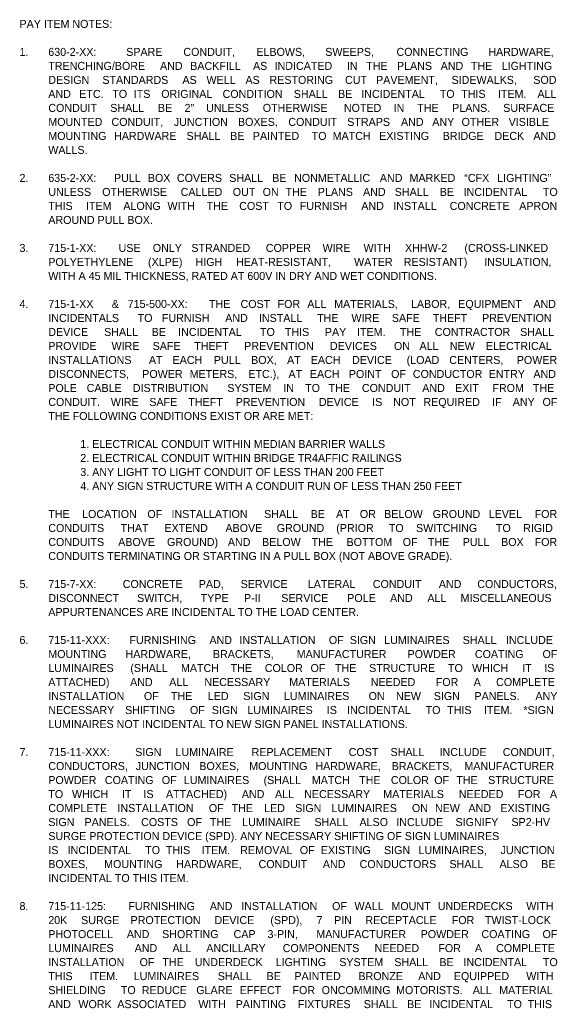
# Model space of a CAD drawing. Extents: x -55 to 2471539, y -90 to 3608906.
# Drawn here: x 27 to 497, y 2532 to 3397 of the extents above; entities that cross this region are included whole.
import ezdxf

# ---------------------------------------------------------------- set-up
doc = ezdxf.new("R2010")
doc.units = 0
doc.layers.add('XSCell', color=7, linetype='Continuous')

msp = doc.modelspace()

# ---------------------------------------------------------------- texts
at = {"layer": 'XSCell'}
for s, p in [('PAY ITEM NOTES:', (26.68, 3389.74)), ('630-2-XX: ', (51.88, 3365.24)), ('SPARE ', (120.08, 3365.24)), ('CONDUIT, ', (170.11, 3365.24)), ('ELBOWS, ', (233.99, 3365.24)), ('SWEEPS, ', (294.28, 3365.24)), ('CONNECTING ', (356.65, 3365.24)), ('1.', (26.68, 3365.24)), ('HARDWARE, ', (437.06, 3365.24)), ('TRENCHING/BORE ', (51.88, 3352.99)), ('AND ', (149.66, 3352.99)), ('BACKFILL ', (176.11, 3352.99)), ('AS ', (231.06, 3352.99)), ('INDICATED ', (249.96, 3352.99)), ('IN ', (313.22, 3352.99)), ('THE ', (330.09, 3352.99)), ('PLANS ', (357.07, 3352.99)), ('AND ', (395.32, 3352.99)), ('THE ', (421.77, 3352.99)), ('LIGHTING ', (448.75, 3352.99)), ('DESIGN ', (51.88, 3340.74)), ('STANDARDS ', (99.2, 3340.74)), ('AS ', (169.29, 3340.74)), ('WELL ', (190.33, 3340.74)), ('AS ', (224.46, 3340.74)), ('RESTORING ', (245.49, 3340.74)), ('CUT ', (311.63, 3340.74)), ('PAVEMENT, ', (338.81, 3340.74)), ('SIDEWALKS, ', (404.84, 3340.74)), ('SOD ', (476.42, 3340.74)), ('AND ', (51.88, 3328.49)), ('ETC. ', (78.98, 3328.49)), ('TO ', (107.88, 3328.49)), ('ITS ', (126.69, 3328.49)), ('ORIGINAL ', (150.74, 3328.49)), ('CONDITION ', (204.43, 3328.49)), ('SHALL ', (266.79, 3328.49)), ('BE ', (305.52, 3328.49)), ('INCIDENTAL ', (325.8, 3328.49)), ('TO ', (394.52, 3328.49)), ('THIS ', (413.34, 3328.49)), ('ITEM. ', (445.46, 3328.49)), ('ALL ', (480.05, 3328.49)), ('CONDUIT ', (51.88, 3316.24)), ('SHALL ', (106.12, 3316.24)), ('BE ', (147.86, 3316.24)), ('2” ', (171.15, 3316.24)), ('UNLESS ', (190.04, 3316.24)), ('OTHERWISE ', (239.61, 3316.24)), ('NOTED ', (310.61, 3316.24)), ('IN ', (354.19, 3316.24)), ('THE ', (374.74, 3316.24)), ('PLANS. ', (405.39, 3316.24)), ('SURFACE ', (450.07, 3316.24)), ('MOUNTED ', (51.88, 3303.99)), ('CONDUIT, ', (107.18, 3303.99)), ('JUNCTION ', (161.77, 3303.99)), ('BOXES, ', (217.91, 3303.99)), ('CONDUIT ', (262.01, 3303.99)), ('STRAPS ', (313.55, 3303.99)), ('AND ', (360.6, 3303.99)), ('ANY ', (388, 3303.99)), ('OTHER ', (413.64, 3303.99)), ('VISIBLE ', (454.83, 3303.99)), ('MOUNTING ', (51.88, 3291.74)), ('HARDWARE ', (109.45, 3291.74)), ('SHALL ', (172.87, 3291.74)), ('BE ', (211.11, 3291.74)), ('PAINTED ', (230.91, 3291.74)), ('TO ', (282.44, 3291.74)), ('MATCH ', (300.77, 3291.74)), ('EXISTING ', (341.5, 3291.74)), ('BRIDGE ', (397.1, 3291.74)), ('DECK ', (442.4, 3291.74)), ('AND ', (476.52, 3291.74)), ('WALLS.', (51.88, 3279.49)), ('2.', (26.68, 3254.99)), ('635-2-XX: ', (51.88, 3254.99)), ('PULL ', (109.38, 3254.99)), ('BOX ', (139.01, 3254.99)), ('COVERS ', (164.44, 3254.99)), ('SHALL ', (210.25, 3254.99)), ('BE ', (247.86, 3254.99)), ('NONMETALLIC ', (267.04, 3254.99)), ('AND ', (342.08, 3254.99)), ('MARKED ', (368.08, 3254.99)), ('“CFX ', (416.03, 3254.99)), ('LIGHTING” ', (444.82, 3254.99)), ('UNLESS ', (51.88, 3242.74)), ('OTHERWISE ', (99.08, 3242.74)), ('CALLED ', (167.72, 3242.74)), ('OUT ', (213.33, 3242.74)), ('ON ', (239.5, 3242.74)), ('THE ', (259.52, 3242.74)), ('PLANS ', (287.82, 3242.74)), ('AND ', (327.38, 3242.74)), ('SHALL ', (355.13, 3242.74)), ('BE ', (394.51, 3242.74)), ('INCIDENTAL ', (415.44, 3242.74)), ('TO ', (484.81, 3242.74)), ('THIS ', (51.88, 3230.49)), ('ITEM ', (84.87, 3230.49)), ('ALONG ', (117.57, 3230.49)), ('WITH ', (156.2, 3230.49)), ('THE ', (190.47, 3230.49)), ('COST ', (218.99, 3230.49)), ('TO ', (252.31, 3230.49)), ('FURNISH ', (272, 3230.49)), ('AND ', (325.85, 3230.49)), ('INSTALL ', (353.83, 3230.49)), ('CONCRETE ', (403.21, 3230.49)), ('APRON ', (464.1, 3230.49)), ('AROUND PULL BOX.', (51.88, 3218.24)), ('3.', (26.68, 3193.74)), ('715-1-XX: ', (51.88, 3193.74)), ('USE ', (113.41, 3193.74)), ('ONLY ', (143.32, 3193.74)), ('STRANDED ', (177.09, 3193.74)), ('COPPER ', (242.27, 3193.74)), ('WIRE ', (291.93, 3193.74)), ('WITH ', (327.81, 3193.74)), ('XHHW-2 ', (364.13, 3193.74)), ('(CROSS-LINKED ', (416.09, 3193.74)), ('POLYETHYLENE ', (51.88, 3181.49)), ('(XLPE) ', (139.17, 3181.49)), ('HIGH ', (180.77, 3181.49)), ('HEAT-RESISTANT, ', (216.17, 3181.49)), ('WATER ', (319.51, 3181.49)), ('RESISTANT) ', (362.99, 3181.49)), ('INSULATION, ', (433.46, 3181.49)), ('WITH A 45 MIL THICKNESS, RATED AT 600V IN DRY AND WET CONDITIONS.', (51.88, 3169.24)), ('4.', (26.68, 3144.74)), ('715-1-XX ', (51.88, 3144.74)), ('& ', (107.43, 3144.74)), ('715-500-XX: ', (121.38, 3144.74)), ('THE ', (192.53, 3144.74)), ('COST ', (220.15, 3144.74)), ('FOR ', (252.57, 3144.74)), ('ALL ', (278.57, 3144.74)), ('MATERIALS, ', (302.12, 3144.74)), ('LABOR, ', (369.32, 3144.74)), ('EQUIPMENT ', (410.7, 3144.74)), ('AND ', (476.52, 3144.74)), ('INCIDENTALS ', (51.88, 3132.49)), ('TO ', (130.09, 3132.49)), ('FURNISH ', (151.32, 3132.49)), ('AND ', (206.72, 3132.49)), ('INSTALL ', (236.24, 3132.49)), ('THE ', (287.15, 3132.49)), ('WIRE ', (317.21, 3132.49)), ('SAFE ', (352.59, 3132.49)), ('THEFT ', (388.42, 3132.49)), ('PREVENTION ', (431.57, 3132.49)), ('DEVICE ', (51.88, 3120.24)), ('SHALL ', (100.73, 3120.24)), ('BE ', (142.37, 3120.24)), ('INCIDENTAL ', (165.56, 3120.24)), ('TO ', (237.2, 3120.24)), ('THIS ', (258.92, 3120.24)), ('PAY ', (293.95, 3120.24)), ('ITEM. ', (322.14, 3120.24)), ('THE ', (359.64, 3120.24)), ('CONTRACTOR ', (390.2, 3120.24)), ('SHALL ', (464.9, 3120.24)), ('PROVIDE ', (51.88, 3107.99)), ('WIRE ', (107.23, 3107.99)), ('SAFE ', (143.2, 3107.99)), ('THEFT ', (179.61, 3107.99)), ('PREVENTION ', (223.35, 3107.99)), ('DEVICES ', (298.41, 3107.99)), ('ON ', (354.43, 3107.99)), ('ALL ', (376.8, 3107.99)), ('NEW ', (403.38, 3107.99)), ('ELECTRICAL ', (434.87, 3107.99)), ('INSTALLATIONS ', (51.88, 3095.74)), ('AT ', (139.95, 3095.74)), ('EACH ', (160.68, 3095.74)), ('PULL ', (196.8, 3095.74)), ('BOX, ', (229.41, 3095.74)), ('AT ', (260.88, 3095.74)), ('EACH ', (281.61, 3095.74)), ('DEVICE ', (317.73, 3095.74)), ('(LOAD ', (365.55, 3095.74)), ('CENTERS, ', (402.86, 3095.74)), ('POWER ', (461.96, 3095.74)), ('DISCONNECTS, ', (51.88, 3083.49)), ('POWER ', (134.11, 3083.49)), ('METERS, ', (175.64, 3083.49)), ('ETC.), ', (226.96, 3083.49)), ('AT ', (262.13, 3083.49)), ('EACH ', (280.84, 3083.49)), ('POINT ', (314.95, 3083.49)), ('OF ', (351.95, 3083.49)), ('CONDUCTOR ', (370.97, 3083.49)), ('ENTRY ', (437.34, 3083.49)), ('AND ', (476.52, 3083.49)), ('POLE ', (51.88, 3071.24)), ('CABLE ', (85.46, 3071.24)), ('DISTRIBUTION ', (125.86, 3071.24)), ('SYSTEM ', (208.6, 3071.24)), ('TO ', (276.72, 3071.24)), ('CONDUIT ', (326.37, 3071.24)), ('FROM ', (440.63, 3071.24)), ('IN ', (257.59, 3071.24)), ('THE ', (297.13, 3071.24)), ('AND ', (379.2, 3071.24)), ('EXIT ', (407.9, 3071.24)), ('THE ', (475.98, 3071.24)), ('CONDUIT. ', (51.88, 3058.99)), ('WIRE ', (106.6, 3058.99)), ('SAFE ', (140.29, 3058.99)), ('THEFT ', (174.43, 3058.99)), ('PREVENTION ', (215.9, 3058.99)), ('DEVICE ', (288.69, 3058.99)), ('IS ', (335.36, 3058.99)), ('NOT ', (353.76, 3058.99)), ('REQUIRED ', (380.24, 3058.99)), ('IF ', (440.35, 3058.99)), ('ANY ', (458.4, 3058.99)), ('OF ', (484.48, 3058.99)), ('THE FOLLOWING CONDITIONS EXIST OR ARE MET:', (51.88, 3046.74)), ('1. ELECTRICAL CONDUIT WITHIN MEDIAN BARRIER WALLS', (79.88, 3022.24)), ('2. ELECTRICAL CONDUIT WITHIN BRIDGE TR4AFFIC RAILINGS', (79.88, 3009.99)), ('3. ANY LIGHT TO LIGHT CONDUIT OF LESS THAN 200 FEET', (79.88, 2997.74)), ('4. ANY SIGN STRUCTURE WITH A CONDUIT RUN OF LESS THAN 250 FEET', (79.88, 2985.49)), ('THE ', (51.88, 2960.99)), ('LOCATION ', (81.48, 2960.99)), ('OF ', (138.62, 2960.99)), ('INSTALLATION ', (159.73, 2960.99)), ('SHALL ', (240.82, 2960.99)), ('BE ', (281.51, 2960.99)), ('AT ', (303.75, 2960.99)), ('OR ', (324.57, 2960.99)), ('BELOW ', (345.84, 2960.99)), ('GROUND ', (388.35, 2960.99)), ('LEVEL ', (437.37, 2960.99)), ('FOR ', (477.59, 2960.99)), ('CONDUITS ', (51.88, 2948.74)), ('THAT ', (115.22, 2948.74)), ('EXTEND ', (153.55, 2948.74)), ('ABOVE ', (206.93, 2948.74)), ('GROUND ', (251.86, 2948.74)), ('(PRIOR ', (303.94, 2948.74)), ('TO ', (349.91, 2948.74)), ('SWITCHING ', (373.75, 2948.74)), ('TO ', (443.69, 2948.74)), ('RIGID ', (467.53, 2948.74)), ('CONDUITS ', (51.88, 2936.49)), ('ABOVE ', (113.04, 2936.49)), ('GROUND) ', (155.79, 2936.49)), ('AND ', (209.04, 2936.49)), ('BELOW ', (239, 2936.49)), ('THE ', (282.41, 2936.49)), ('BOTTOM ', (312.9, 2936.49)), ('OF ', (362.12, 2936.49)), ('THE ', (384.12, 2936.49)), ('PULL ', (414.62, 2936.49)), ('BOX ', (448.21, 2936.49)), ('FOR ', (477.59, 2936.49)), ('CONDUITS TERMINATING OR STARTING IN A PULL BOX (NOT ABOVE GRADE).', (51.88, 2924.24)), ('5.', (26.68, 2899.74)), ('715-7-XX: ', (51.88, 2899.74)), ('CONCRETE ', (117.03, 2899.74)), ('PAD, ', (183.6, 2899.74)), ('SERVICE ', (220.24, 2899.74)), ('LATERAL ', (279, 2899.74)), ('CONDUIT ', (335.93, 2899.74)), ('AND ', (393.71, 2899.74)), ('CONDUCTORS, ', (427.37, 2899.74)), ('DISCONNECT ', (51.88, 2887.49)), ('SWITCH, ', (129.64, 2887.49)), ('TYPE ', (185.25, 2887.49)), ('P-II ', (223.15, 2887.49)), ('SERVICE ', (255.82, 2887.49)), ('POLE ', (313.56, 2887.49)), ('AND ', (351.06, 2887.49)), ('ALL ', (383.69, 2887.49)), ('MISCELLANEOUS ', (412.79, 2887.49)), ('APPURTENANCES ARE INCIDENTAL TO THE LOAD CENTER.', (51.88, 2875.24)), ('6.', (26.68, 2850.74)), ('715-11-XXX: ', (51.88, 2850.74)), ('FURNISHING ', (122.93, 2850.74)), ('AND ', (192.93, 2850.74)), ('INSTALLATION ', (219.18, 2850.74)), ('OF ', (297.45, 2850.74)), ('SIGN ', (315.74, 2850.74)), ('LUMINAIRES ', (345.9, 2850.74)), ('SHALL ', (414.59, 2850.74)), ('INCLUDE ', (452.46, 2850.74)), ('MOUNTING ', (51.88, 2838.49)), ('HARDWARE, ', (119.48, 2838.49)), ('BRACKETS, ', (195.97, 2838.49)), ('MANUFACTURER ', (269.31, 2838.49)), ('POWDER ', (366.37, 2838.49)), ('COATING ', (425.27, 2838.49)), ('OF ', (484.48, 2838.49)), ('LUMINAIRES ', (51.88, 2826.24)), ('(SHALL ', (123.68, 2826.24)), ('MATCH ', (168.01, 2826.24)), ('THE ', (211.48, 2826.24)), ('COLOR ', (241.38, 2826.24)), ('OF ', (281.43, 2826.24)), ('THE ', (302.84, 2826.24)), ('STRUCTURE ', (332.74, 2826.24)), ('TO ', (401.75, 2826.24)), ('WHICH ', (422.82, 2826.24)), ('IT ', (466.72, 2826.24)), ('IS ', (485.95, 2826.24)), ('ATTACHED) ', (51.88, 2813.99)), ('AND ', (123.47, 2813.99)), ('ALL ', (157.72, 2813.99)), ('NECESSARY ', (188.45, 2813.99)), ('MATERIALS ', (262.81, 2813.99)), ('NEEDED ', (334.12, 2813.99)), ('FOR ', (391.05, 2813.99)), ('A ', (424.22, 2813.99)), ('COMPLETE ', (443.85, 2813.99)), ('INSTALLATION ', (51.88, 2801.74)), ('OF ', (135.58, 2801.74)), ('THE ', (159.31, 2801.74)), ('LED ', (191.53, 2801.74)), ('SIGN ', (222.55, 2801.74)), ('LUMINAIRES ', (258.15, 2801.74)), ('ON ', (332.27, 2801.74)), ('NEW ', (356.22, 2801.74)), ('SIGN ', (389.3, 2801.74)), ('PANELS. ', (424.89, 2801.74)), ('ANY ', (478.27, 2801.74)), ('NECESSARY ', (51.88, 2789.49)), ('SHIFTING ', (119.12, 2789.49)), ('OF ', (175.87, 2789.49)), ('SIGN ', (195.05, 2789.49)), ('LUMINAIRES ', (226.1, 2789.49)), ('IS ', (295.69, 2789.49)), ('INCIDENTAL ', (313.39, 2789.49)), ('TO ', (382.15, 2789.49)), ('THIS ', (400.99, 2789.49)), ('ITEM. ', (433.14, 2789.49)), ('*SIGN ', (467.76, 2789.49)), ('LUMINAIRES NOT INCIDENTAL TO NEW SIGN PANEL INSTALLATIONS.', (51.88, 2777.24)), ('7.', (26.68, 2752.74)), ('715-11-XXX: ', (51.88, 2752.74)), ('SIGN ', (127.98, 2752.74)), ('LUMINAIRE ', (163.19, 2752.74)), ('REPLACEMENT ', (229.85, 2752.74)), ('COST ', (314.81, 2752.74)), ('SHALL ', (351.45, 2752.74)), ('INCLUDE ', (394.36, 2752.74)), ('CONDUIT, ', (449.72, 2752.74)), ('CONDUCTORS, ', (51.88, 2740.49)), ('JUNCTION ', (128.38, 2740.49)), ('BOXES, ', (184.07, 2740.49)), ('MOUNTING ', (227.74, 2740.49)), ('HARDWARE, ', (285.65, 2740.49)), ('BRACKETS, ', (352.46, 2740.49)), ('MANUFACTURER ', (416.11, 2740.49)), ('POWDER ', (51.88, 2728.24)), ('COATING ', (101.4, 2728.24)), ('OF ', (151.24, 2728.24)), ('LUMINAIRES ', (170.57, 2728.24)), ('(SHALL ', (240.3, 2728.24)), ('MATCH ', (282.55, 2728.24)), ('THE ', (323.94, 2728.24)), ('COLOR ', (351.76, 2728.24)), ('OF ', (389.72, 2728.24)), ('THE ', (409.05, 2728.24)), ('STRUCTURE ', (436.87, 2728.24)), ('TO ', (51.88, 2715.99)), ('WHICH ', (72.65, 2715.99)), ('IT ', (116.27, 2715.99)), ('IS ', (135.21, 2715.99)), ('ATTACHED) ', (154.85, 2715.99)), ('AND ', (221.27, 2715.99)), ('ALL ', (250.34, 2715.99)), ('NECESSARY ', (275.89, 2715.99)), ('MATERIALS ', (345.07, 2715.99)), ('NEEDED ', (411.2, 2715.99)), ('FOR ', (462.95, 2715.99)), ('A ', (490.95, 2715.99)), ('COMPLETE ', (51.88, 2703.74)), ('INSTALLATION ', (112.45, 2703.74)), ('OF ', (192.38, 2703.74)), ('THE ', (212.33, 2703.74)), ('LED ', (240.77, 2703.74)), ('SIGN ', (268.01, 2703.74)), ('LUMINAIRES ', (299.83, 2703.74)), ('ON ', (370.17, 2703.74)), ('NEW ', (390.34, 2703.74)), ('AND ', (419.64, 2703.74)), ('EXISTING ', (447.54, 2703.74)), ('SIGN ', (51.88, 2691.49)), ('PANELS. ', (83.62, 2691.49)), ('COSTS ', (133.14, 2691.49)), ('OF ', (173.39, 2691.49)), ('THE ', (193.26, 2691.49)), ('LUMINAIRE ', (221.62, 2691.49)), ('SHALL ', (284.81, 2691.49)), ('ALSO ', (324.26, 2691.49)), ('INCLUDE ', (356.45, 2691.49)), ('SIGNIFY ', (408.34, 2691.49)), ('SP2-HV ', (457.26, 2691.49)), ('SURGE PROTECTION DEVICE (SPD). ANY NECESSARY SHIFTING OF SIGN LUMINAIRES ', (51.88, 2679.24)), ('IS ', (51.88, 2666.99)), ('INCIDENTAL ', (68.77, 2666.99)), ('TO ', (136.7, 2666.99)), ('THIS ', (154.73, 2666.99)), ('ITEM. ', (186.07, 2666.99)), ('REMOVAL ', (219.87, 2666.99)), ('OF ', (272.05, 2666.99)), ('EXISTING ', (290.42, 2666.99)), ('SIGN ', (345.72, 2666.99)), ('LUMINAIRES, ', (375.96, 2666.99)), ('JUNCTION ', (447.79, 2666.99)), ('BOXES, ', (51.88, 2654.74)), ('MOUNTING ', (100.75, 2654.74)), ('HARDWARE, ', (163.88, 2654.74)), ('CONDUIT ', (235.9, 2654.74)), ('AND ', (292.19, 2654.74)), ('CONDUCTORS ', (324.36, 2654.74)), ('SHALL ', (403.02, 2654.74)), ('ALSO ', (446.81, 2654.74)), ('BE ', (483.35, 2654.74)), ('INCIDENTAL TO THIS ITEM.', (51.88, 2642.49)), ('8.', (26.68, 2617.99)), ('715-11-125: ', (51.88, 2617.99)), ('FURNISHING ', (121.99, 2617.99)), ('AND ', (193.26, 2617.99)), ('INSTALLATION ', (220.77, 2617.99)), ('OF ', (300.31, 2617.99)), ('WALL ', (319.87, 2617.99)), ('MOUNT ', (352.21, 2617.99)), ('UNDERDECKS ', (392.8, 2617.99)), ('WITH ', (470.23, 2617.99)), ('20K ', (51.88, 2605.74)), ('SURGE ', (80.64, 2605.74)), ('PROTECTION ', (123.89, 2605.74)), ('DEVICE ', (197.33, 2605.74)), ('(SPD), ', (246.25, 2605.74)), ('7 ', (286.69, 2605.74)), ('PIN ', (302.02, 2605.74)), ('RECEPTACLE ', (329.39, 2605.74)), ('FOR ', (405.04, 2605.74)), ('TWIST-LOCK ', (434.05, 2605.74)), ('PHOTOCELL ', (51.88, 2593.49)), ('AND ', (120.6, 2593.49)), ('SHORTING ', (151.52, 2593.49)), ('CAP ', (214.05, 2593.49)), ('3-PIN, ', (243.77, 2593.49)), ('MANUFACTURER ', (286.49, 2593.49)), ('POWDER ', (377.83, 2593.49)), ('COATING ', (431, 2593.49)), ('OF ', (484.48, 2593.49)), ('LUMINAIRES ', (51.88, 2581.24)), ('AND ', (127.45, 2581.24)), ('ALL ', (160.58, 2581.24)), ('ANCILLARY ', (190.18, 2581.24)), ('COMPONENTS ', (257.03, 2581.24)), ('NEEDED ', (337.48, 2581.24)), ('FOR ', (393.29, 2581.24)), ('A ', (425.34, 2581.24)), ('COMPLETE ', (443.85, 2581.24)), ('INSTALLATION ', (51.88, 2568.99)), ('OF ', (131.79, 2568.99)), ('THE ', (151.73, 2568.99)), ('UNDERDECK ', (180.16, 2568.99)), ('LIGHTING ', (250.89, 2568.99)), ('SYSTEM ', (306.55, 2568.99)), ('SHALL ', (354.73, 2568.99)), ('BE ', (394.24, 2568.99)), ('INCIDENTAL ', (415.3, 2568.99)), ('TO ', (484.81, 2568.99)), ('THIS ', (51.88, 2556.74)), ('ITEM. ', (88.03, 2556.74)), ('LUMINAIRES ', (126.65, 2556.74)), ('SHALL ', (200.23, 2556.74)), ('BE ', (242.98, 2556.74)), ('PAINTED ', (267.29, 2556.74)), ('BRONZE ', (323.33, 2556.74)), ('AND ', (375.7, 2556.74)), ('EQUIPPED ', (406.84, 2556.74)), ('WITH ', (470.23, 2556.74)), ('SHIELDING ', (51.88, 2544.49)), ('TO ', (115.39, 2544.49)), ('REDUCE ', (133.72, 2544.49)), ('GLARE ', (181.41, 2544.49)), ('EFFECT ', (219.38, 2544.49)), ('FOR ', (265.61, 2544.49)), ('ONCOMMING ', (291.16, 2544.49)), ('MOTORISTS. ', (356.32, 2544.49)), ('ALL ', (423.44, 2544.49)), ('MATERIAL ', (446.54, 2544.49)), ('AND ', (51.88, 2532.24)), ('WORK ', (78.23, 2532.24)), ('ASSOCIATED ', (112.3, 2532.24)), ('WITH ', (183.26, 2532.24)), ('PAINTING ', (215.9, 2532.24)), ('FIXTURES ', (270.22, 2532.24)), ('SHALL ', (327.97, 2532.24)), ('BE ', (365.95, 2532.24)), ('INCIDENTAL ', (385.47, 2532.24)), ('TO ', (453.45, 2532.24)), ('THIS ', (471.51, 2532.24))]:
    msp.add_text(s, height=7, dxfattribs=at).set_placement(p)

doc.saveas('drawing.dxf')
